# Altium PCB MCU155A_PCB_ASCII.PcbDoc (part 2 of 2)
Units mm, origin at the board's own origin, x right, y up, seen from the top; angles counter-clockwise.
Board outline 32 x 29 mm, 4 copper layers (Top Layer, Layer 1, Layer 2, Bottom Layer), stack 1.567 mm thick; 102 components, 61 nets, 283 pads, 121 vias.
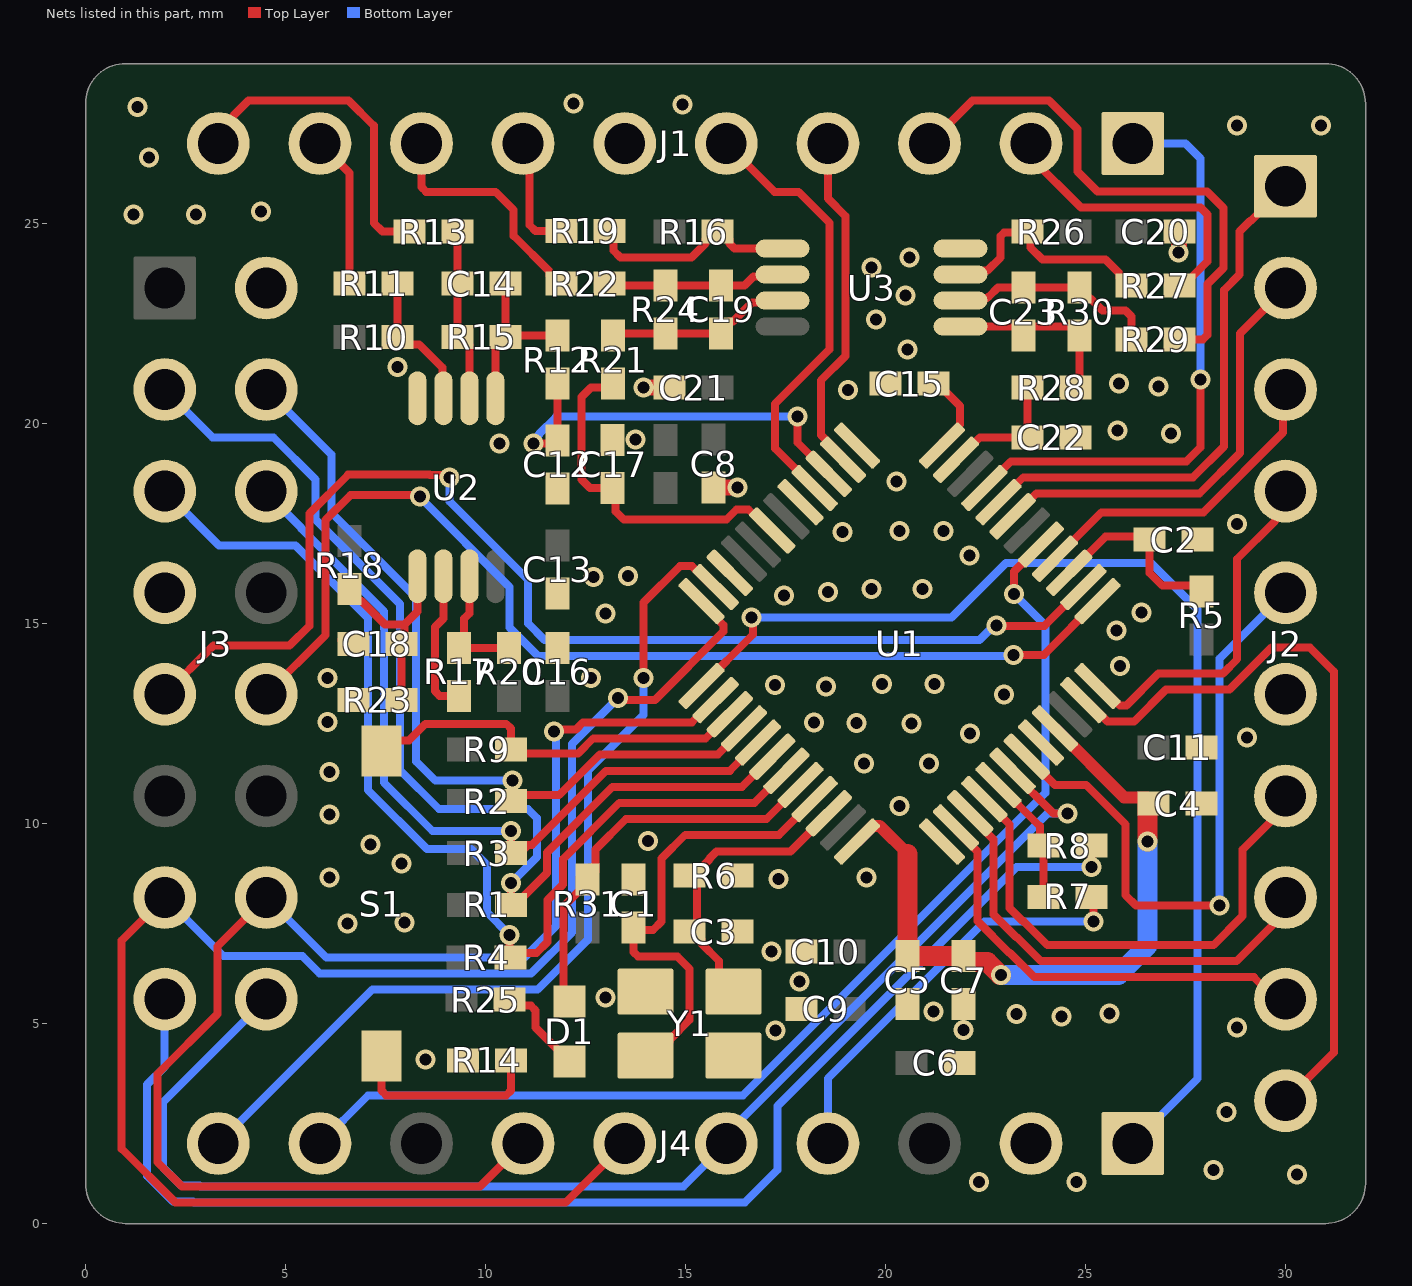
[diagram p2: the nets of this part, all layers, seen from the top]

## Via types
v1: diameter 0.5, hole 0.3, Top Layer to Bottom Layer, tented both sides, 121 vias

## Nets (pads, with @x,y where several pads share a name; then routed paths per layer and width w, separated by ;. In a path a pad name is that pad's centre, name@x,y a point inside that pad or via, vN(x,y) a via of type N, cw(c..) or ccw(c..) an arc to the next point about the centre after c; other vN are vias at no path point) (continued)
BOOT_MODE: R9.1 S1.1 U1.27 | length 10
  Top Layer w0.2: S1.1@7.4,11.81 7.667,12.077 8.082,12.077 8.498,12.493 10.518,12.493 10.635,12.376 R9.1@10.635,11.852 10.734,11.753 12.316,11.753 12.694,12.131 15.506,12.131 U1.27@16.107,12.732
GND: C1.1 C2.2 C3.2 C4.1 C5.1 C6.2 C7.1 C8.2 C9.2 C10.2 C11.2 C12.2 C13.2 C15.2 C16.2 C17.2 C18.2 C20.2 C21.2 C22.2 J1.6 J2.6 J3.2 J3.7 J4.2 R6.1 R14.2 R23.1 U1.13 U1.17 U1.22 U1.37 U1.44 U2.4 U3.4 Y1.2 Y1.4 | length 2
  Top Layer w0.4: C18.2@6.499,14.591 6.599,14.491 C18.2@6.699,14.491 ; v1(13.95,20.9) C21.2@14.6,20.9 ; C8.2@15.7,18.4 15.702,18.403 16.297,18.403 v1(16.3,18.405) ; v1(27.324,24.279) 27.337,24.292 27.337,24.787 C20.2@27.35,24.8
  other v1: 22.338,1.041 24.769,1.041 30.286,1.225 28.2,1.343 28.519,2.794 8.5,4.1 17.25,4.83 21.948,4.833 28.793,4.9 24.401,5.179 23.278,5.237 25.6,5.256 21.2,5.3 13,5.65 17.85,6.05 17.15,6.8 6.55,7.5 7.976,7.52 17.33,8.61 6.1,8.651 19.521,8.651 7.9,9 7.121,9.48 14.057,9.558 6.1,10.232 20.351,10.438 6.1,11.283 19.468,11.502 21.087,11.495 29.041,12.149 22.113,12.254 19.271,12.517 20.644,12.5 6.05,12.544 18.212,12.531 22.961,13.226 18.511,13.43 17.231,13.465 19.912,13.493 21.23,13.493 12.639,13.64 6.05,13.644 25.858,13.944 25.769,14.826 12.999,15.256 26.4,15.273 17.467,15.705 18.566,15.79 19.65,15.86 20.924,15.86 12.706,16.163 13.563,16.187 22.1,16.703 18.919,17.293 20.351,17.312 21.448,17.312 28.793,17.491 20.278,18.551 10.35,19.5 13.75,19.6 27.141,19.751 25.798,19.825 19.068,20.843 26.826,20.924 25.841,20.998 7.794,21.408 20.55,21.85 19.766,22.606 20.501,23.202 19.65,23.9 20.6,24.15 1.199,25.224 2.76,25.224 4.391,25.3 1.582,26.646 28.793,27.454 30.891,27.454 1.301,27.909 14.923,27.975 12.198,27.998
IPM_FAULT: J4.1 U1.25 | length 28.5
  Top Layer w0.2: U1.25@15.4,13.439 16.691,14.731 16.691,15.108 v1(16.65,15.15)
  Bottom Layer w0.2: v1(16.65,15.15) 21.65,15.15 23.015,16.515 26.634,16.515 27.8,15.35 27.8,3.62 J4.1@26.18,2
IU_AD: C12.1 R12.2 U1.15 | length 10.7
  Top Layer w0.2: v1(11.2,19.5) 11.723,19.5 C12.1@11.8,19.577 R12.2@11.8,21 ; v1(17.804,20.171) 17.804,19.52 U1.15@18.582,18.743
  Bottom Layer w0.2: v1(11.2,19.5) 11.2,19.581 11.337,19.718 11.337,19.741 11.767,20.171 v1(17.804,20.171)
IU_N: J1.10 R13.1 | length 8.2
  Top Layer w0.2: J1.10@3.32,27 3.32,27.32 4.075,28.075 6.577,28.075 7.207,27.445 7.207,25.014 7.421,24.8 R13.1@8.1,24.8
IU_P: J1.9 R11.1 | length 3.8
  Top Layer w0.2: J1.9@5.86,27 6.6,26.26 R11.1@6.6,23.5
IV_AD: C17.1 R21.2 U1.19 | length 8.7
  Top Layer w0.2: R21.2@13.189,21 13.089,20.9 12.639,20.9 12.4,20.661 12.4,18.599 12.61,18.388 C17.1@13.18,18.388 13.253,18.316 13.253,17.806 13.463,17.596 16.021,17.596 16.28,17.855 16.57,17.855 U1.19@17.097,17.328
IV_N: J1.8 R22.1 | length 6
  Top Layer w0.2: J1.8@8.4,27 8.4,25.911 8.517,25.794 10.253,25.794 10.705,25.342 10.705,24.693 11.598,23.8 11.598,23.7 11.798,23.5 R22.1@11.898,23.5
IV_P: J1.7 R19.1 | length 3
  Top Layer w0.2: J1.7@10.94,27 11.105,26.835 11.105,24.958 11.248,24.814 R19.1@11.898,24.814
IW_AD: C22.1 R28.2 U1.11 | length 3.3
  Top Layer w0.2: U1.11@21.764,19.096 21.802,19.096 22.362,19.656 C22.1@23.55,19.656 R28.2@23.55,20.9
IW_N: J1.3 R29.1 | length 13.6
  Top Layer w0.2: J1.3@21.1,27 22.175,28.075 24.085,28.075 24.8,27.36 24.8,26.3 25.299,25.8 28.04,25.8 28.45,25.39 28.45,23.891 28.05,23.491 28.05,22.219 27.933,22.102 R29.1@27.35,22.102
IW_P: J1.2 R27.1 | length 7.5
  Top Layer w0.2: J1.2@23.64,27 23.64,26.646 24.886,25.4 25.625,25.4 26.674,25.4 27.874,25.4 28.05,25.224 28.05,24.056 27.65,23.656 27.65,23.651 27.45,23.451 R27.1@27.35,23.451
LED1C: D1.2 R31.1 U1.32 | length 10.3
  Top Layer w0.2: D1.2@12.1,5.55 11.95,5.7 11.95,7.924 12.325,8.3 12.35,8.3 12.35,8.648 12.6,8.898 R31.1@12.62,8.898 ; R31.1@12.55,8.6 12.75,8.8 12.75,9.35 13.518,10.118 17.028,10.118 U1.32@17.875,10.964
MISC_IO: J4.9 U1.5 | length 28.6
  Top Layer w0.2: v1(23.213,15.737) 23.213,16.303 U1.5@23.885,16.975
  Bottom Layer w0.2: J4.9@5.86,2 7.066,3.207 16.437,3.207 24,10.769 24,14.951 v1(23.213,15.737)
MOTOR_TEMP_AD: J2.3 U1.4 | length 8.1
  Top Layer w0.2: U1.4@24.239,16.621 25.399,17.782 27.946,17.782 29.939,19.775 29.939,20.789 J2.3@30,20.85
NetC1_2: C1.2 U1.33 Y1.3 | length 11.7
  Top Layer w0.2: C1.2@13.7,7.399 13.7,6.792 13.817,6.675 14.794,6.675 15.1,6.369 15.1,5.094 14.596,4.591 14.596,4.535 14.121,4.06 Y1.3@13.996,4.06 ; C1.2@13.784,7.334 14.183,7.334 14.4,7.551 14.4,9.123 14.995,9.718 17.335,9.718 U1.33@18.228,10.611
NetC3_1: C3.1 R6.2 U1.34 Y1.1 | length 7.4
  Top Layer w0.2: C3.1@15.1,7.3 15.2,7.3 15.4,7.1 15.4,7 15.842,6.558 15.842,6.158 Y1.1@16.2,5.8 ; C3.1@15.289,7.3 15.289,8.55 15.32,8.58 15.32,8.819 15.6,9.098 15.6,9.123 15.775,9.298 17.623,9.298 U1.34@18.582,10.257
NetC4_2: C4.2 C5.2 C7.2 U1.36 U1.45 | length 17.5
  Top Layer w0.3: U1.36@19.289,9.55 19.678,9.939 19.855,9.939 20.551,9.243 ; U1.45@24.239,12.379 25.967,10.65 26.55,10.65 C4.2@26.563,10.637
  Top Layer w0.5: 20.551,9.243 C5.2@20.551,6.683 C7.2@21.948,6.683 21.948,6.583 21.998,6.533 22.549,6.533 22.866,6.215 v1(22.886,6.215) ; v1(26.55,9.55) 26.55,10.157 26.55,10.45 26.6,10.5 C4.2@26.7,10.5
  Bottom Layer w0.5: v1(22.886,6.215) 25.82,6.215 26.55,6.945 v1(26.55,9.55)
NetC14_1: C14.1 R13.2 R15.1 U2.2 | length 4.3
  Top Layer w0.2: R13.2@9.3,24.8 C14.1@9.3,23.5 R15.1@9.3,22.158 9.398,22.158 9.598,21.958 U2.2@9.598,20.631
NetC14_2: C14.2 R12.1 R15.2 U2.1 | length 4.3
  Top Layer w0.2: U2.1@10.248,20.631 10.248,21.958 10.448,22.158 R15.2@10.5,22.158 ; C14.2@10.5,23.5 R15.2@10.5,22.158 ; R12.1@11.8,22.2 10.542,22.2 R15.2@10.5,22.158
NetC15_1: C15.1 U1.12 | length 2.1
  Top Layer w0.2: C15.1@21.2,21 21.3,21 21.862,20.438 21.862,19.972 21.41,19.52 U1.12@21.41,19.45
NetC18_1: C18.1 R18.1 R23.2 U2.5 | length 5.1
  Top Layer w0.2: R18.1@6.6,15.863 6.6,15.763 6.8,15.563 6.9,15.563 7.489,14.974 7.974,14.974 ; C18.1@7.899,14.491 7.974,14.566 7.974,14.974 ; R23.2@7.9,13.094 C18.1@7.899,14.491 ; U2.5@8.298,16.181 8.298,15.298 7.974,14.974
NetC19_1: C19.1 R22.2 R24.1 U3.6 | length 4.4
  Top Layer w0.2: R22.2@13.198,23.5 13.247,23.452 R24.1@14.501,23.452 16.471,23.452 16.697,23.677 17.377,23.677 U3.6@17.425,23.725
NetC19_2: C19.2 R21.1 R24.2 U3.7 | length 4.7
  Top Layer w0.2: R21.1@13.189,22.2 13.24,22.252 R24.2@14.501,22.252 C19.2@15.887,22.252 15.887,22.352 16.087,22.552 16.187,22.552 16.663,23.027 17.377,23.027 U3.7@17.425,23.075
NetC23_1: C23.1 R29.2 R30.1 U3.2 | length 5.3
  Top Layer w0.2: U3.2@21.875,23.075 21.913,23.113 22.504,23.113 22.559,23.168 22.581,23.168 22.813,23.4 C23.1@23.451,23.4 R30.1@24.853,23.4 24.853,23.3 25.028,23.125 25.128,23.125 25.427,22.826 26.003,22.826 26.15,22.679 R29.2@26.15,22.102
NetC23_2: C23.2 R28.1 R30.2 U3.1 | length 4.4
  Top Layer w0.2: U3.1@21.875,22.425 24.653,22.425 24.853,22.225 R30.2@24.853,22.2 24.853,21.004 R28.1@24.75,20.9
NetD1_1: D1.1 R25.2 | length 2.4
  Top Layer w0.2: R25.2@10.6,5.6 10.754,5.446 11.133,5.446 11.25,5.329 11.25,4.9 D1.1@12.1,4.05
NetR10_1: R10.1 R11.2 U2.3 | length 3.6
  Top Layer w0.2: R11.2@7.8,23.5 R10.1@7.8,22.158 7.982,21.976 8.342,21.976 8.921,21.397 8.921,20.658 U2.3@8.948,20.631
NetR14_1: R14.1 S1.2 | length 5
  Top Layer w0.2: S1.2@7.4,4.19 7.4,3.324 7.517,3.207 10.518,3.207 10.635,3.324 R14.1@10.635,4.082
NetR16_1: R16.1 R19.2 U3.5 | length 5.4
  Top Layer w0.2: R19.2@13.098,24.814 13.194,24.719 13.194,24.332 13.374,24.152 15.151,24.152 15.5,24.5 15.5,24.6 15.7,24.8 R16.1@15.8,24.8 15.9,24.8 16.1,24.6 16.1,24.5 16.225,24.375 U3.5@17.425,24.375
NetR17_1: R17.1 R20.1 U2.7 | length 3.2
  Top Layer w0.2: U2.7@9.598,16.181 9.598,15.256 9.467,15.125 9.467,14.624 9.336,14.493 R17.1@9.336,14.393 R20.1@10.592,14.393
NetR17_2: R17.2 U2.6 | length 3.6
  Top Layer w0.2: U2.6@8.948,16.181 8.948,15.129 8.736,14.917 8.736,13.31 8.853,13.193 R17.2@9.336,13.193
NetR26_1: R26.1 R27.2 U3.3 | length 5.8
  Top Layer w0.2: U3.3@21.875,23.725 22.379,23.725 22.479,23.825 22.552,23.825 22.875,24.147 22.875,24.683 22.967,24.775 23.525,24.775 R26.1@23.55,24.8 23.628,24.721 23.628,24.396 23.925,24.1 25.5,24.1 25.85,23.751 25.85,23.651 26.05,23.451 R27.2@26.15,23.451
PC_RX: J3.9 U1.2 | length 30.1
  Top Layer w0.2: J3.9@1.98,13.23 3.199,14.449 5.103,14.449 5.595,14.941 5.595,17.713 5.6,17.718 5.6,17.753 6.568,18.72 8.596,18.72 8.606,18.71 9.042,18.71 v1(9.1,18.652) ; v1(22.77,14.951) 22.783,14.938 23.969,14.938 U1.2@24.946,15.914
  Bottom Layer w0.2: v1(9.1,18.652) 9.1,18.055 11.068,16.086 11.068,14.997 11.475,14.59 22.353,14.59 22.713,14.951 v1(22.77,14.951)
PC_TX: J3.10 U1.1 | length 27.4
  Top Layer w0.2: J3.10@4.52,13.23 5.999,14.709 5.999,15.982 6,15.984 6,17.587 6.621,18.207 8.331,18.207 v1(8.368,18.17) ; v1(23.195,14.22) 23.958,14.22 U1.1@25.299,15.561
  Bottom Layer w0.2: v1(8.368,18.17) 8.368,18.149 10.6,15.917 10.6,14.9 11.309,14.19 23.165,14.19 v1(23.195,14.22)
PWM_UH: J2.7 U1.40 | length 12.9
  Top Layer w0.2: U1.40@22.471,10.611 23.1,9.982 23.1,7.891 23.425,7.565 23.445,7.565 24.053,6.958 28.197,6.958 28.925,7.686 28.925,9.346 30,10.421 J2.7@30,10.69
PWM_UL: J2.8 U1.39 | length 11.4
  Top Layer w0.2: U1.39@22.117,10.257 22.117,10.187 22.7,9.604 22.7,7.726 23.26,7.165 23.279,7.165 23.887,6.558 28.773,6.558 30,7.785 J2.8@30,8.15
PWM_VH: J2.9 U1.38 | length 11.1
  Top Layer w0.2: U1.38@21.764,9.904 21.764,9.833 22.3,9.297 22.3,7.56 23.094,6.765 23.114,6.765 23.721,6.158 29.208,6.158 29.755,5.61 J2.9@30,5.61
PWM_VL: J2.10 U1.47 | length 18.7
  Top Layer w0.2: U1.47@24.946,13.086 25.017,13.086 25.55,12.553 26.217,12.553 27.015,13.35 28.599,13.35 29.649,14.4 30.606,14.4 31.206,13.8 31.206,4.276 J2.10@30,3.07
PWM_WH: J2.4 U1.48 | length 8.9
  Top Layer w0.2: U1.48@25.299,13.439 25.37,13.439 25.857,12.953 26.022,12.953 26.82,13.75 28.434,13.75 28.793,14.109 28.793,16.619 29.741,17.567 29.741,18.052 J2.4@30,18.31
PWM_WL: J2.5 U1.43 | length 15.9
  Top Layer w0.2: U1.43@23.532,11.672 24.239,10.964 25.017,10.964 26,9.981 26,8.209 26.258,7.95 v1(28.35,7.95)
  Bottom Layer w0.2: v1(28.35,7.95) 28.35,14.12 J2.5@30,15.77
RELAY: J4.10 U1.23 | length 22.8
  Top Layer w0.2: v1(13.95,13.64) 13.95,15.525 14.866,16.441 15.156,16.441 15.683,15.914 U1.23@15.753,15.914
  Bottom Layer w0.2: J4.10@3.32,2 7.17,5.85 11.305,5.85 12.56,7.105 12.56,11.327 13.95,12.717 v1(13.95,13.64)
SPI_CLK: J3.13 J4.6 U1.24 | length 42.6
  Top Layer w0.2: J3.13@1.98,8.15 0.905,7.075 0.905,1.867 2.247,0.525 12.005,0.525 J4.6@13.48,2 ; v1(13.311,13.137) 13.357,13.09 14.237,13.09 15.944,14.797 15.944,14.963 15.4,15.507 U1.24@15.4,15.561
  Bottom Layer w0.2: J3.13@1.98,8.15 3.445,6.685 5.419,6.685 5.854,6.25 11.14,6.25 12.16,7.27 12.16,11.986 v1(13.311,13.137)
SPI_PICO: J3.14 J4.7 U1.26 | length 35
  Top Layer w0.2: J3.14@4.52,8.15 3.3,6.93 3.3,5.237 1.795,3.732 1.795,1.542 2.413,0.925 9.865,0.925 J4.7@10.94,2 ; v1(11.711,12.303) 11.76,12.353 12.261,12.353 12.439,12.531 15.156,12.531 15.711,13.086 U1.26@15.753,13.086
  Bottom Layer w0.2: J3.14@4.52,8.15 6.02,6.65 10.974,6.65 11.76,7.436 11.76,12.254 v1(11.711,12.303)
SPI_POCI: R7.2 R8.2 U1.41 | length 3.3
  Top Layer w0.2: U1.41@22.825,10.964 23.856,9.933 23.856,9.544 R8.2@23.95,9.45 R7.2@23.95,8.165
SPI_POCI(AI): J4.4 R7.1 | length 10.6
  Top Layer w0.2: R7.1@25.15,8.165 25.2,8.115 v1(25.2,7.55) v1@25.251,7.55
  Bottom Layer w0.2: J4.4@18.56,2 18.56,3.632 22.478,7.55 v1(25.2,7.55)
SPI_POCI(DAC): J3.15 R8.1 | length 33.4
  Top Layer w0.2: v1(25.15,8.915) R8.1@25.15,9.45
  Bottom Layer w0.2: J3.15@1.98,5.61 1.98,3.917 1.54,3.477 1.54,1.194 2.184,0.55 2.684,0.55 2.709,0.525 16.482,0.525 17.3,1.343 17.3,2.937 23.278,8.915 v1(25.15,8.915)
SPI_PTE: J3.16 J4.5 U1.42 | length 33.9
  Top Layer w0.2: U1.42@23.178,11.318 23.178,11.272 24.2,10.25 v1(24.55,10.25)
  Bottom Layer w0.2: J3.16@4.52,5.61 1.94,3.03 1.94,1.398 2.388,0.95 2.849,0.95 2.874,0.925 14.945,0.925 J4.5@16.02,2 16.02,2.223 24.047,10.25 v1(24.55,10.25)
TCK: J3.4 R2.1 U1.28 | length 20.5
  Top Layer w0.2: R2.1@10.635,10.557 R2.1@10.67,10.592 ; v1(10.67,11.078) R2.1@10.67,10.592 ; U1.28@16.461,12.379 15.813,11.731 12.859,11.731 11.842,10.714 10.791,10.714 R2.1@10.67,10.592
  Bottom Layer w0.2: J3.4@4.52,20.85 6.15,19.22 6.15,17.768 8.266,15.652 8.266,11.556 8.744,11.078 v1(10.67,11.078)
TDI: J3.5 R4.1 U1.31 | length 26.8
  Top Layer w0.2: v1(10.6,7.217) 10.6,6.666 R4.1@10.619,6.647 10.731,6.759 11.269,6.759 11.55,7.039 11.55,8.09 11.935,8.475 11.935,9.109 13.343,10.518 16.721,10.518 U1.31@17.521,11.318
  Bottom Layer w0.2: J3.5@1.98,18.31 3.337,16.952 5.251,16.952 7.066,15.138 7.066,10.834 8.539,9.361 9.636,9.361 10.035,8.962 10.035,7.782 v1(10.6,7.217)
TDO: J3.6 R3.1 U1.29 | length 19.9
  Top Layer w0.2: v1(10.635,9.807) R3.1@10.635,9.262 10.868,9.262 11.068,9.462 11.156,9.462 13.012,11.318 16.107,11.318 U1.29@16.714,11.925
  Bottom Layer w0.2: J3.6@4.52,18.31 4.52,18.266 5.4,17.386 5.4,17.369 7.466,15.303 7.466,11.022 8.68,9.807 v1(10.635,9.807)
TIPM_AD: J2.2 U1.7 | length 10.9
  Top Layer w0.2: U1.7@23.178,17.682 23.202,17.682 23.776,18.256 27.854,18.256 28.859,19.26 28.859,22.249 J2.2@30,23.39
TMS: J3.3 R1.1 U1.30 | length 27.6
  Top Layer w0.2: v1(10.635,8.512) R1.1@10.635,7.967 10.735,7.967 11.535,8.767 11.535,9.275 13.178,10.918 16.414,10.918 U1.30@17.168,11.672
  Bottom Layer w0.2: J3.3@1.98,20.85 3.173,19.657 4.693,19.657 5.75,18.6 5.75,17.602 7.866,15.486 7.866,11.334 8.842,10.357 11.06,10.357 11.285,10.133 11.285,9.162 v1(10.635,8.512)
VDC_AD: J2.1 U1.8 | length 13.4
  Top Layer w0.2: U1.8@22.825,18.036 23.445,18.656 27.689,18.656 28.459,19.426 28.459,23.334 28.85,23.725 28.85,24.8 29.109,25.06 29.129,25.06 J2.1@30,25.93
VU_AD: J1.4 U1.14 | length 8.6
  Top Layer w0.2: J1.4@18.56,27 18.56,25.624 19,25.184 19,21.691 18.389,21.081 18.389,19.713 18.935,19.167 U1.14@18.935,19.096
VV_AD: J1.1 U1.9 | length 14.9
  Top Layer w0.2: U1.9@22.471,18.389 23.138,19.056 27.523,19.056 27.874,19.407 v1(27.874,21.1)
  Bottom Layer w0.2: J1.1@26.18,27 27.5,27 27.874,26.626 v1(27.874,21.1)
VW_AD: J1.5 U1.16 | length 11
  Top Layer w0.2: J1.5@16.02,27 17.226,25.794 17.825,25.794 18.6,25.019 18.6,21.857 17.236,20.494 17.236,19.381 U1.16@18.228,18.389
XRSn: C2.1 R5.1 U1.3 | length 4.7
  Top Layer w0.2: U1.3@24.592,16.268 25.496,17.171 26.528,17.171 C2.1@26.6,17.1 26.6,16.269 26.919,15.95 27.75,15.95 R5.1@27.9,15.8
pads on no net: J3.8 J3.11 J3.12 J4.8 LBL1.0 M46.1 M46.2 M47.1 M49.1 M49.2 M49_1.2 M49_2.2 M50.1 M50.2 M51.1 M51.2 M52.1 M52.2 M53.1 M54.1 M55.1 M56.2 M56_1.2 M56_2.2 M57.2 M57_1.2 M57_2.2 M57_2_1.2 M57_2_2.2 M58.2 M58_1.2 M58_2.2 M58_2_1.2 M59.2 M59_1.2 M60.2 M60_1.2 M61.2 U1.6 U1.10 U1.20 U1.21

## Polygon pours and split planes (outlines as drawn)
GND on Top Layer "T-G" (solid, remove dead copper, pour order 0): 1.399,28.6 ccw(c1.399,27.6) 0.4,27.6 0.4,1.4 ccw(c1.4,1.4) 1.4,0.4 30.6,0.4 ccw(c30.6,1.4) 31.6,1.4 31.6,27.6 ccw(c30.6,27.6) 30.6,28.6
GND on Layer 1 "G1-G" (solid, remove dead copper, pour order 1): 1.399,28.6 ccw(c1.399,27.6) 0.4,27.6 0.4,1.4 ccw(c1.4,1.4) 1.4,0.4 30.6,0.4 ccw(c30.6,1.4) 31.6,1.4 31.6,27.6 ccw(c30.6,27.6) 30.6,28.6
GND on Layer 2 "G2-G" (solid, remove dead copper, pour order 2): 1.399,28.6 ccw(c1.399,27.6) 0.4,27.6 0.4,1.4 ccw(c1.4,1.4) 1.4,0.4 30.6,0.4 ccw(c30.6,1.4) 31.6,1.4 31.6,27.6 ccw(c30.6,27.6) 30.6,28.6
GND on Bottom Layer "B-G" (solid, remove dead copper, pour order 3): 1.399,28.6 ccw(c1.399,27.6) 0.4,27.6 0.4,1.4 ccw(c1.4,1.4) 1.4,0.4 30.6,0.4 ccw(c30.6,1.4) 31.6,1.4 31.6,27.6 ccw(c30.6,27.6) 30.6,28.6

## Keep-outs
Keep-Out Layer:
  text ".Layer_Name" at -75.865,-32.255 h1.52

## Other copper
Top Layer:
  text ".Layer_Name" at -75.865,-32.255 h1.52
Bottom Layer:
  text ".Layer_Name" at -75.865,-32.255 h1.52

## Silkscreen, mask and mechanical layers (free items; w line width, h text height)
Top Overlay:
  lines w0.1: 22.86,4.717 28.81,4.717 ; 22.86,5.376 28.81,5.376 ; 25.554,3.991 25.554,6.741 ; 22.81,3.97 28.81,3.97 28.81,6.77 22.81,6.77 22.81,3.97
  text "1" at 5.226,10.521 h0.4
  text "S1 /  / 1-OFF / 0-ON" at 22.644,4.106 h0.4
  text "Boot Mode / Flash / SCI/Wait" at 25.679,4.106 h0.4
  text "0" at 5.226,3.907 h0.4
  text "拼板" at 295.809,-23.566 h5
  text ".Layer_Name" at -75.865,-32.255 h1.52
Bottom Overlay:
  text "'.PRJ_Title' / '.PRJ_Number'.PCB_Rev" at 17.3,4.55 h1.52 r270
  text ".Layer_Name" at -75.865,-32.255 h1.52
Top Paste:
  text ".Layer_Name" at -75.865,-32.255 h1.52
Bottom Paste:
  text ".Layer_Name" at -75.865,-32.255 h1.52
Top Solder:
  text ".Layer_Name" at -75.865,-32.255 h1.52
  text ".Layer_Name" at -75.865,-32.255 h1.52
Bottom Solder:
  text ".Layer_Name" at -75.865,-32.255 h1.52
Drill Guide:
  text ".Layer_Name" at -75.865,-32.255 h1.52
M1 Board Outline:
  drawing of 210 lines, arcs and shapes, not listed
  text ".Layer_Name" at -75.865,-32.255 h1.52
M2 Board Dimensions:
  rectangle: -90.52,-17.435 -87.345,-14.26
  rectangle: -87.345,-20.61 -77.82,-17.435
  lines w0.178: -90.52,-17.435 -65.12,-17.435 ; -87.345,-20.61 -87.345,-14.26 ; -84.17,-20.61 -84.17,-14.26 ; -77.82,-20.61 -77.82,-14.26 ; -71.47,-20.61 -71.47,-14.26 ; -90.52,-20.61 -65.12,-20.61 -65.12,-14.26 -90.52,-14.26 -90.52,-20.61
  text ".Layer_Name" at -75.865,-32.255 h1.52
M3 3D STEP Top:
  text ".Layer_Name" at -75.865,-32.255 h1.52
M4 3D STEP Bottom:
  text ".Layer_Name" at -75.865,-32.255 h1.52
M5 Assembly Top:
  lines w0.254: -97.937,-34.076 69.703,-34.076 ; -97.937,-28.911 69.754,-28.911 ; -97.937,-23.746 -97.937,-39.24 3.79,-39.24 69.754,-39.24 69.754,-23.746 -97.924,-23.746 -97.924,-39.24 -57.907,-39.24 ; -35.326,-39.24 -35.326,-23.746 ; -3.144,-28.911 -3.144,-23.746 ; 18.192,-28.911 18.192,-23.746 ; 33.99,-39.406 33.99,-34.254
  text "COMPONENTS MARKED 'DNP' SHOULD NOT BE POPULATED." at -61.221,-18.539 h0.8
  text "ASSEMBLY VARIANT:" at -61.234,-21.473 h0.8
  text ".VariantName" at -34.92,-21.473 h0.8
  text "PCB VIEWED FROM TOP SIDE" at -96.324,-27.103 h1.52
  text "BOARD #:" at -33.421,-27.103 h1.52
  text ".PRJ_Number" at -19.565,-27.103 h1.52
  text "REV:" at 1.885,-27.103 h1.52
  text ".PCB_Rev" at 9.289,-27.103 h1.52
  text "SVN REV:" at 23.17,-27.103 h1.52
  text ".VersionControl_RevNumber" at 36.022,-27.103 h1.52
  text "TID #:" at -33.421,-32.268 h1.52
  text ".TID" at -19.565,-32.268 h1.52
  text "PLOT NAME =" at -96.324,-37.484 h1.52
  text ".plot_File_Name" at -75.865,-37.484 h1.52
  text "GENERATED    :" at -33.37,-37.484 h1.52
  text ".Print_Date" at -11.285,-37.484 h1.52
  text ".Print_Time" at 7.232,-37.484 h1.52
  text "TEXAS INSTRUMENTS" at 39.35,-37.484 h1.52
M6 Assembly Bottom:
  lines w0.254: -97.95,-28.924 69.741,-28.924 ; -97.899,-34.088 69.741,-34.088 ; -62.187,-39.418 -62.187,-34.266 ; -46.388,-28.924 -46.388,-23.759 ; -25.052,-28.924 -25.052,-23.759 ; 7.13,-39.253 7.13,-23.759 ; 29.711,-39.253 69.728,-39.253 69.728,-23.759 -97.95,-23.759 -97.95,-39.253 -31.986,-39.253 69.741,-39.253 69.741,-23.759
  text "COMPONENTS MARKED 'DNP' SHOULD NOT BE POPULATED." at 64.47,-18.527 h0.8
  text ".VariantName" at 37.953,-21.473 h0.8
  text "ASSEMBLY VARIANT:" at 64.343,-21.473 h0.8
  text ".VersionControl_RevNumber" at -64.219,-27.116 h1.52
  text "SVN REV:" at -51.366,-27.116 h1.52
  text ".PCB_Rev" at -37.485,-27.116 h1.52
  text "REV:" at -30.081,-27.116 h1.52
  text ".PRJ_Number" at -8.631,-27.116 h1.52
  text "BOARD #:" at 5.225,-27.116 h1.52
  text "PCB VIEWED FROM BOTTOM SIDE" at 68.128,-27.116 h1.52
  text ".TID" at -8.631,-32.281 h1.52
  text "TID #:" at 5.225,-32.281 h1.52
  text "TEXAS INSTRUMENTS" at -67.546,-37.496 h1.52
  text ".Print_Time" at -35.428,-37.496 h1.52
  text ".Print_Date" at -16.911,-37.496 h1.52
  text "GENERATED    :" at 5.174,-37.496 h1.52
  text ".plot_File_Name" at 47.668,-37.496 h1.52
  text "PLOT NAME =" at 68.128,-37.496 h1.52
M9 Title Sheet:
  lines w0.254: -103.004,16.005 -97.924,16.005 ; -103.004,76.33 -97.924,76.33 ; -103.004,136.655 -97.924,136.655 ; -39.504,-44.32 -39.504,-39.24 ; -39.504,191.9 -39.504,196.98 ; 23.996,-44.32 23.996,-39.24 ; 23.996,191.9 23.996,196.98 ; 70.033,-39.24 70.033,-23.746 196.589,-23.746 ; 87.496,-44.32 87.496,-39.24 ; 87.496,191.9 87.496,196.98 ; 150.996,-44.32 150.996,-39.24 ; 150.996,191.9 150.996,196.98 ; 196.589,-39.24 196.589,-23.746 ; 196.589,-31.366 272.789,-31.366 ; 196.589,-16.126 272.789,-16.126 ; 196.614,-1.039 272.814,-1.039 ; 214.496,-44.32 214.496,-39.24 ; 214.496,191.9 214.496,196.98 ; 234.816,-38.986 234.816,-23.746 ; 272.789,-23.746 196.589,-23.746 ; 272.789,-8.506 196.589,-8.506 ; 272.916,-8.76 272.916,-39.24 ; 272.916,11.674 196.614,11.674 196.589,11.674 196.589,-1.039 196.589,-8.506 ; 272.916,16.005 277.996,16.005 ; 272.916,76.33 277.996,76.33 ; 272.916,136.655 277.996,136.655 ; 196.589,-23.746 196.589,-8.506 ; 272.916,-39.24 272.916,191.9 -97.924,191.9 -97.924,-39.24 272.916,-39.24 ; -103.004,-44.32 -103.004,196.98 277.996,196.98 277.996,-44.32 -103.004,-44.32
  text "1" at -71.728,193.678 h1.78
  text "2" at -8.339,193.678 h1.78
  text "3" at 54.891,193.678 h1.78
  text "4" at 118.56,193.678 h1.78
  text "5" at 182.034,193.678 h1.78
  text "6" at 245.661,193.678 h1.78
  text "A" at -101.099,164.645 h1.78
  text "A" at 274.821,164.645 h1.78
  text "B" at -101.099,104.193 h1.78
  text "B" at 274.821,104.193 h1.78
  text "C" at -101.099,43.868 h1.78
  text "C" at 274.821,43.868 h1.78
  text "PROJECT TITLE:" at 197.605,-3.401 h1.14
  text ".PRJ_Title" at 198.875,-6.788 h1.78
  text "DESIGNED FOR:" at 197.605,-11.046 h1.14
  text ".PRJ_Customer" at 198.875,-14.602 h1.78
  text "D" at -101.099,-16.33 h1.78
  text "D" at 274.821,-16.33 h1.78
  text "FILE NAME:" at 197.605,-18.666 h1.14
  text ".PCB_File_Name_No_Path" at 198.875,-21.714 h1.78
  text "Texas Instruments (TI) and/or its licensors do not warrant the accuracy or completeness of this specification" at 71.379,-25.825 h1.14
  text "ENGINEER:" at 197.605,-26.032 h1.14
  text "LAYOUT BY:" at 235.832,-26.032 h1.14
  text "or any information contained therein. TI and/or its licensors do not warrant that this design will meet" at 70.237,-28.687 h1.14
  text ".PRJ_Engineer" at 198.875,-29.969 h1.78
  text ".PCB_Layout" at 237.114,-29.969 h1.78
  text "the specifications, will be suitable for your application or fit for any particular purpose, or will operate in" at 70.237,-31.549 h1.14
  text ".Layer_Name" at -75.865,-32.255 h1.52
  text "ALTIUM DESIGNER VERSION:" at 235.832,-33.906 h1.14
  text "an implementation. TI and/or its licensors do not warrant that the design is production worthy. You should" at 70.237,-34.41 h1.14
  text "completely validate and test your design implementation to confirm the system functionality for your application." at 71.379,-37.272 h1.14
  text ".print_Scale" at 198.875,-37.293 h1.78
  text ".Application_BuildNumber" at 237.114,-37.293 h1.78
  text "1" at -71.728,-42.542 h1.78
  text "2" at -8.339,-42.542 h1.78
  text "3" at 54.891,-42.542 h1.78
  text "4" at 118.56,-42.542 h1.78
  text "5" at 182.034,-42.542 h1.78
  text "6" at 245.661,-42.542 h1.78
M10 Fab Notes:
  drawing of 189 lines, arcs and shapes, not listed
  text "DESIGN INFORMATION" at 223.983,150.997 h1.52
  text "MIN. TRACK WIDTH:" at 207.611,147.641 h1.52
  text "8" at 235.456,147.641 h1.52
  text "MIL" at 239.387,147.641 h1.52
  text "MIN. CLEARANCE:" at 207.611,144.489 h1.52
  text "MIL" at 239.387,144.489 h1.52
  text "8" at 235.68,144.35 h1.52
  text "MIN. VIA PAD SIZE:" at 207.611,141.336 h1.52
  text "19" at 234.694,141.336 h1.52
  text "MIL" at 239.387,141.336 h1.52
  text "0.05mm (2MIL)" at 225.264,138.036 h1.52
  text "MINIMUM ANNULAR RING" at 199.249,137.827 h1.52
  text "EXTERNAL" at 243.247,137.827 h1.52
  text "PER" at 204.329,135.03 h1.52
  text "IPC-D-275 CLASS 2 LEVEL C" at 209.917,135.03 h1.52
  text "MIL, HOLES" at 247.718,132.478 h1.52
  text "+/-" at 237.749,132.26 h1.52
  text "+/-" at 259.441,132.26 h1.52
  text "REGISTRATION TOLERANCES:" at 199.249,132.233 h1.52
  text "METAL" at 229.723,132.233 h1.52
  text "5" at 244.358,132.233 h1.52
  text "3" at 265.517,132.233 h1.52
  text "MIL" at 268.47,132.233 h1.52
  text "HOLE SIZE TOLERANCE (UNLESS OTHERWISE SPECIFIED):" at 199.249,129.736 h1.52
  text "+/-" at 259.441,129.663 h1.52
  text "3" at 265.517,129.636 h1.52
  text "MIL" at 268.47,129.636 h1.52
  text "MATERIAL:" at 197.35,126.139 h1.52
  text "FR-4 High Tg" at 222.405,122.875 h1.52
  text "X" at 218.736,122.672 h1.52
  text "FR-4" at 208.043,122.557 h1.52
  text "OTHER" at 245.838,122.557 h1.52
  text "62 MIL (1.6mm) +/-10%" at 216.174,118.924 h1.52
  text "X" at 213.123,118.862 h1.52
  text "THICKNESS:" at 199.249,118.716 h1.52
  text "OTHER" at 248.81,118.716 h1.52
  text "TOLERANCE:" at 199.249,115.202 h1.52
  text "X" at 220.794,115.202 h1.52
  text "ANSI IPC-6012 TYPE 3 CLASS 2" at 225.315,115.202 h1.52
  text "OTHER +/-" at 225.315,111.54 h1.52
  text "BOW & TWIST:" at 199.249,107.852 h1.52
  text "X" at 220.794,107.852 h1.52
  text "ANSI IPC-6012 TYPE 3 CLASS 2" at 225.315,107.852 h1.52
  text "OTHER +/-" at 225.315,104.126 h1.52
  text "DRILLING:" at 197.35,100.808 h1.52
  text "NC_DRILL FILES" at 242.079,98.137 h1.52
  text "REFERENCE:" at 199.249,98.037 h1.52
  text "X" at 215.942,98.034 h1.52
  text "AS SHOWN" at 220.464,98.037 h1.52
  text "X" at 238.828,98.037 h1.52
  text "OTHER" at 249.648,94.423 h1.52
  text "PTH COPPER THICKNESS:" at 199.24,94.334 h1.52
  text "X" at 228.177,94.334 h1.52
  text "20-30 um" at 231.428,94.334 h1.52
  text "BOARD FINISH:" at 197.35,90.585 h1.52
  text "SILKSCREEN:" at 201.292,87.788 h1.52
  text "X" at 225.62,87.788 h1.52
  text "TOP" at 228.592,87.788 h1.52
  text "X" at 238.574,87.788 h1.52
  text "BOTTOM" at 241.571,87.788 h1.52
  text "SILKSCREEN COLOR:" at 201.292,83.846 h1.52
  text "X" at 225.594,83.846 h1.52
  text "WHITE" at 228.592,83.846 h1.52
  text "OTHER" at 241.571,83.846 h1.52
  text "X" at 228.922,80.202 h1.52
  text "GREEN" at 231.919,80.202 h1.52
  text "OTHER" at 247.616,80.202 h1.52
  text "SOLDER RESIST COLOR:" at 201.292,80.028 h1.52
  text "X" at 228.922,76.284 h1.52
  text "MATTE" at 231.919,76.284 h1.52
  text "SEMI-GLOSS" at 247.604,76.268 h1.52
  text "IMMERSION GOLD (ENIG)" at 224.299,71.896 h1.52
  text "ENEPIG" at 258.272,71.712 h1.52
  text "SURFACE FINISH:" at 197.35,71.687 h1.52
  text "HASL" at 251.717,68.312 h1.52
  text "IMM. TIN/SILVER OR EQUIV" at 205.72,68.199 h1.52
  text "X" at 237.558,68.099 h1.52
  text "OTHER" at 242.079,68.099 h1.52
  text "ARRAY/PANEL:" at 197.35,64.153 h1.52
  text "CUT AND TRIM PER M1 BOARD OUTLINE" at 224.299,63.944 h1.52
  text "N.C. ROUTE" at 224.299,60.49 h1.52
  text "X" at 241.774,60.49 h1.52
  text "V. SCORE" at 246.295,60.49 h1.52
  text "CERTIFICATION:" at 197.35,57.21 h1.52
  text "MATERIALS AND WORKMANSHIP FOR ALL PCBS" at 215.765,57.21 h1.52
  text "TO MEET OR EXCEED THE REQUIREMENTS OF:" at 215.765,54.821 h1.52
  text "X" at 206.557,51.554 h1.52
  text "ANSI IPC-A-600F CLASS ->" at 209.808,51.554 h1.52
  text "X" at 251.668,51.554 h1.52
  text "2" at 254.462,51.554 h1.52
  text "1" at 246.461,51.516 h1.52
  text "3" at 263.453,51.516 h1.52
  text "X" at 227.182,47.803 h1.52
  text "RoHS" at 230.433,47.803 h1.52
  text "OTHER" at 246.801,47.803 h1.52
  text "PER ORDER" at 256.886,47.803 h1.52
  text "ALL BOARDS MUST MEET OR EXCEED UL94-V0 REQUIREMENTS." at 198.049,43.895 h1.52
  text "PCB MUST BEAR THE UL94V-0 UL REGISTERED MATERIAL ID NUMBER" at 198.049,40.947 h1.52
  text "ADDITIONAL REQUIREMENTS:" at 197.35,36.644 h1.52
  text "MICROSECTION:" at 199.249,33.923 h1.52
  text "YES" at 222.254,33.923 h1.52
  text "REQUIRED" at 244.136,30.257 h1.52
  text "BARE BOARD ELEC. TEST:" at 199.249,30.185 h1.52
  text "NONE" at 232.414,30.185 h1.52
  text "X" at 241.139,30.185 h1.52
  text "PER ORDER" at 259.173,30.185 h1.52
  text "XX MIL VIAS REQUIRE NON-CONDUCTIVE FILL AND PLANARIZE" at 203.52,24.979 h1.5
  text "XX MIL VIAS REQUIRE CONDUCTIVE FILL AND PLANARIZE" at 203.723,22.338 h1.52
  text "OUTER XX MIL TRACES REQUIRE 50 OHM SINGLE-ENDED IMPEDANCE" at 203.698,18.188 h1.47
  text "LAYER 2 & 3 (INNER LAYERS) XX MIL WIDE, XX MIL SPACE / TRACES REQUIRE 100 OHM DIFFERENTIAL IMPEDANCE" at 203.495,12.201 h1.52
  text ".Layer_Name" at -75.865,-32.255 h1.52
M11 Gerber Information:
  lines w0.254: -97.937,-34.076 69.703,-34.076 ; -97.937,-28.911 69.754,-28.911 ; -97.937,-23.746 -97.937,-39.24 3.79,-39.24 69.754,-39.24 69.754,-23.746 -97.924,-23.746 -97.924,-39.24 -57.907,-39.24 ; -35.326,-39.24 -35.326,-23.746 ; -3.144,-28.911 -3.144,-23.746 ; 18.192,-28.911 18.192,-23.746 ; 33.99,-39.406 33.99,-34.254
  text "ALL ARTWORK VIEWED FROM TOP SIDE" at -96.324,-27.103 h1.52
  text "BOARD #:" at -33.421,-27.103 h1.52
  text ".PRJ_Number" at -19.565,-27.103 h1.52
  text "REV:" at 1.885,-27.103 h1.52
  text ".PCB_Rev" at 9.289,-27.103 h1.52
  text "SVN REV:" at 23.17,-27.103 h1.52
  text ".VersionControl_RevNumber" at 36.022,-27.103 h1.52
  text "LAYER NAME =" at -96.324,-32.255 h1.52
  text "TID #:" at -33.421,-32.268 h1.52
  text ".TID" at -19.565,-32.268 h1.52
  text "PLOT NAME =" at -96.324,-37.484 h1.52
  text ".plot_File_Name" at -75.865,-37.484 h1.52
  text "GENERATED    :" at -33.37,-37.484 h1.52
  text ".Print_Date" at -11.285,-37.484 h1.52
  text ".Print_Time" at 7.232,-37.484 h1.52
  text "TEXAS INSTRUMENTS" at 39.35,-37.484 h1.52
M12 Stackup:
  drawing of 196 lines, arcs and shapes, not listed
  text "Layer" at 158.694,189.574 h1.52
  text "Name" at 165.072,189.574 h1.52
  text "Material" at 177.406,189.574 h1.52
  text "Thickness" at 188.489,189.574 h1.52
  text "Constant" at 197.593,189.574 h1.52
  text "Board Layer Stack" at 206.019,189.574 h1.52
  text "Top Overlay" at 165.072,186.526 h1.52
  text "Top Solder" at 165.072,183.478 h1.52
  text "Solder Resist" at 177.406,183.478 h1.52
  text "0.010mm" at 188.489,183.478 h1.52
  text "3.5" at 197.593,183.478 h1.52
  text "1" at 158.694,180.43 h1.52
  text "Top Layer" at 165.072,180.43 h1.52
  text "CF-004" at 177.406,180.43 h1.52
  text "0.035mm" at 188.489,180.43 h1.52
  text "Dielectric 1" at 165.072,177.382 h1.52
  text "PP-023" at 177.406,177.382 h1.52
  text "0.218mm" at 188.489,177.382 h1.52
  text "4.5" at 197.593,177.382 h1.52
  text "2" at 158.693,174.334 h1.52
  text "Layer 1" at 165.072,174.334 h1.52
  text "CF-004" at 177.406,174.334 h1.52
  text "0.035mm" at 188.489,174.334 h1.52
  text "Dielectric1" at 165.072,171.286 h1.52
  text "Core-042" at 177.406,171.286 h1.52
  text "0.991mm" at 188.489,171.286 h1.52
  text "4.6" at 197.593,171.286 h1.52
  text "3" at 158.694,168.238 h1.52
  text "Layer 2" at 165.072,168.238 h1.52
  text "CF-004" at 177.406,168.238 h1.52
  text "0.035mm" at 188.489,168.238 h1.52
  text "Dielectric 2" at 165.072,165.19 h1.52
  text "PP-023" at 177.406,165.19 h1.52
  text "0.218mm" at 188.489,165.19 h1.52
  text "4.5" at 197.593,165.19 h1.52
  text "4" at 158.694,162.142 h1.52
  text "Bottom Layer" at 165.072,162.142 h1.52
  text "CF-004" at 177.406,162.142 h1.52
  text "0.035mm" at 188.489,162.142 h1.52
  text "Bottom Solder" at 165.072,159.094 h1.52
  text "Solder Resist" at 177.406,159.094 h1.52
  text "0.010mm" at 188.489,159.094 h1.52
  text "3.5" at 197.593,159.094 h1.52
  text "Bottom Overlay" at 165.072,156.046 h1.52
  text ".Layer_Name" at -75.865,-32.255 h1.52
M13 Component Bodies Top:
  text ".Layer_Name" at -75.865,-32.255 h1.52
M14 Component Bodies Bottom:
  text ".Layer_Name" at -75.865,-32.255 h1.52
M15 Courtyards Top:
  text ".Layer_Name" at -75.865,-32.255 h1.52
M16 Courtyards Bottom:
  text ".Layer_Name" at -75.865,-32.255 h1.52
Drill Drawing:
  circle w0.254: c-91.564,89.741 r0.847
  lines w0.254: -92.411,92.704 -90.718,92.704 -90.718,94.397 -92.411,94.397 -92.411,92.704 ; -92.411,98.207 -90.718,98.207 -91.564,96.514 -92.411,98.207
  lines w0.381: -93.93,87.751 86.412,87.751 ; -93.93,99.181 86.412,99.181 ; -79.938,83.941 -79.938,102.991 ; -65.209,83.941 -65.209,102.991 ; -37.278,83.941 -37.278,102.991 ; -24.428,83.941 -24.428,102.991 ; -5.79,83.941 -5.79,102.991 ; 32.299,83.941 32.299,102.991 ; 47.281,83.941 47.281,102.991 ; 66.224,83.941 66.224,102.991 ; -93.93,83.941 86.412,83.941 86.412,102.991 -93.93,102.991 -93.93,83.941
  text "Symbol" at -91.644,100.324 h1.83
  text "Count" at -78.795,100.324 h1.83
  text "Hole Size" at -64.066,100.324 h1.83
  text "Plated" at -36.135,100.324 h1.83
  text "Hole Type" at -23.285,100.324 h1.83
  text "Drill Layer Pair" at -4.647,100.324 h1.83
  text "Via/Pad" at 33.442,100.324 h1.83
  text "Pad Shape" at 48.424,100.324 h1.83
  text "Template" at 67.367,100.324 h1.83
  text "4" at -78.795,96.514 h1.52
  text "2.000mm (78.74mil)" at -64.066,96.514 h1.52
  text "NPTH" at -36.135,96.514 h1.52
  text "Round" at -23.285,96.514 h1.52
  text "Top Layer - Bottom Layer" at -4.647,96.514 h1.52
  text "Pad" at 33.442,96.514 h1.52
  text "Rounded" at 48.424,96.514 h1.52
  text "c200hn200" at 67.367,96.514 h1.52
  text "46" at -78.795,92.704 h1.52
  text "1.020mm (40.16mil)" at -64.066,92.704 h1.52
  text "PTH" at -36.135,92.704 h1.52
  text "Round" at -23.285,92.704 h1.52
  text "Top Layer - Bottom Layer" at -4.647,92.704 h1.52
  text "Pad" at 33.442,92.704 h1.52
  text "(Mixed)" at 48.424,92.704 h1.52
  text "(Mixed)" at 67.367,92.704 h1.52
  text "121" at -78.795,88.894 h1.52
  text "0.300mm (11.81mil)" at -64.066,88.894 h1.52
  text "PTH" at -36.135,88.894 h1.52
  text "Round" at -23.285,88.894 h1.52
  text "Top Layer - Bottom Layer" at -4.647,88.894 h1.52
  text "Via" at 33.442,88.894 h1.52
  text "Rounded" at 48.424,88.894 h1.52
  text "v50h30m0mx0" at 67.367,88.894 h1.52
  text "171 Total" at -78.795,85.084 h1.52
  text ".Layer_Name" at -75.865,-32.255 h1.52
M17 Embedded Cavity:
  text ".Layer_Name" at -75.865,-32.255 h1.52
M18 Embedded Assembly:
  text ".Layer_Name" at -75.865,-32.255 h1.52
M19 Embedded Keepout:
  text ".Layer_Name" at -75.865,-32.255 h1.52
